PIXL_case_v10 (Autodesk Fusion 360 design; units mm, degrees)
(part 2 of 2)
sketch "Sketch6" plane through (0, 0, -6.5) normal (0, 0, 1) x axis (1, 0, 0)
  line L1 (-0.6, -24.9) -> (-14.6, -24.9)
  line L2 (-0.6, -10.9) -> (-0.6, -24.9)
  line L3 (-14.6, -10.9) -> (-0.6, -10.9)
  line L4 (-14.6, -24.9) -> (-14.6, -10.9)
extrude "Extrude6" new body sketch "Sketch6" along normal blind 6.2 bodies "DS3231 14x14 (no header)"
work_plane "WorkPlane7" AlongDistance -6.4 ExtraOffset 0
sketch "Sketch7" plane through (0, 0, -6.4) normal (0, 0, 1) x axis (1, 0, 0)
  line L1 (-15.9, -21) -> (-21.9, -21)
  line L2 (-15.9, -15) -> (-15.9, -21)
  line L3 (-21.9, -15) -> (-15.9, -15)
  line L4 (-21.9, -21) -> (-21.9, -15)
extrude "Extrude7" new body sketch "Sketch7" along normal blind 3.6 bodies "Side tact switch 6x6 (right angle)"
work_plane "WorkPlane8" AlongDistance -5.6 ExtraOffset 0
sketch "Sketch8" plane through (0, 0, -5.6) normal (0, 0, 1) x axis (1, 0, 0)
  line L1 (-21.89, -19.2) -> (-22.4, -19.2)
  line L2 (-21.89, -16.8) -> (-21.89, -19.2)
  line L3 (-22.4, -16.8) -> (-21.89, -16.8)
  line L4 (-22.4, -19.2) -> (-22.4, -16.8)
extrude "Extrude8" add sketch "Sketch8" along normal blind 2
work_plane "WorkPlane9" AlongDistance -6.8 ExtraOffset 0
sketch "Sketch9" plane through (0, 0, -6.8) normal (0, 0, 1) x axis (1, 0, 0)
  circle C1 centre (11, -15.3) radius 10
extrude "Extrude9" new body sketch "Sketch9" along normal blind 0.5 bodies "Piezo disc 20mm"
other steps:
create_component "CreateComponent1"
create_component "CreateComponent65"
create_component "CreateComponent66"
create_component "CreateComponent67"
named bodies: "Shell", "Back", "LiPo 30x20x5", "Vibration motor 10x2.7", "XIAO ESP32-S3 (upside down)", "DS3231 14x14 (no header)", "Side tact switch 6x6 (right angle)", "Piezo disc 20mm"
